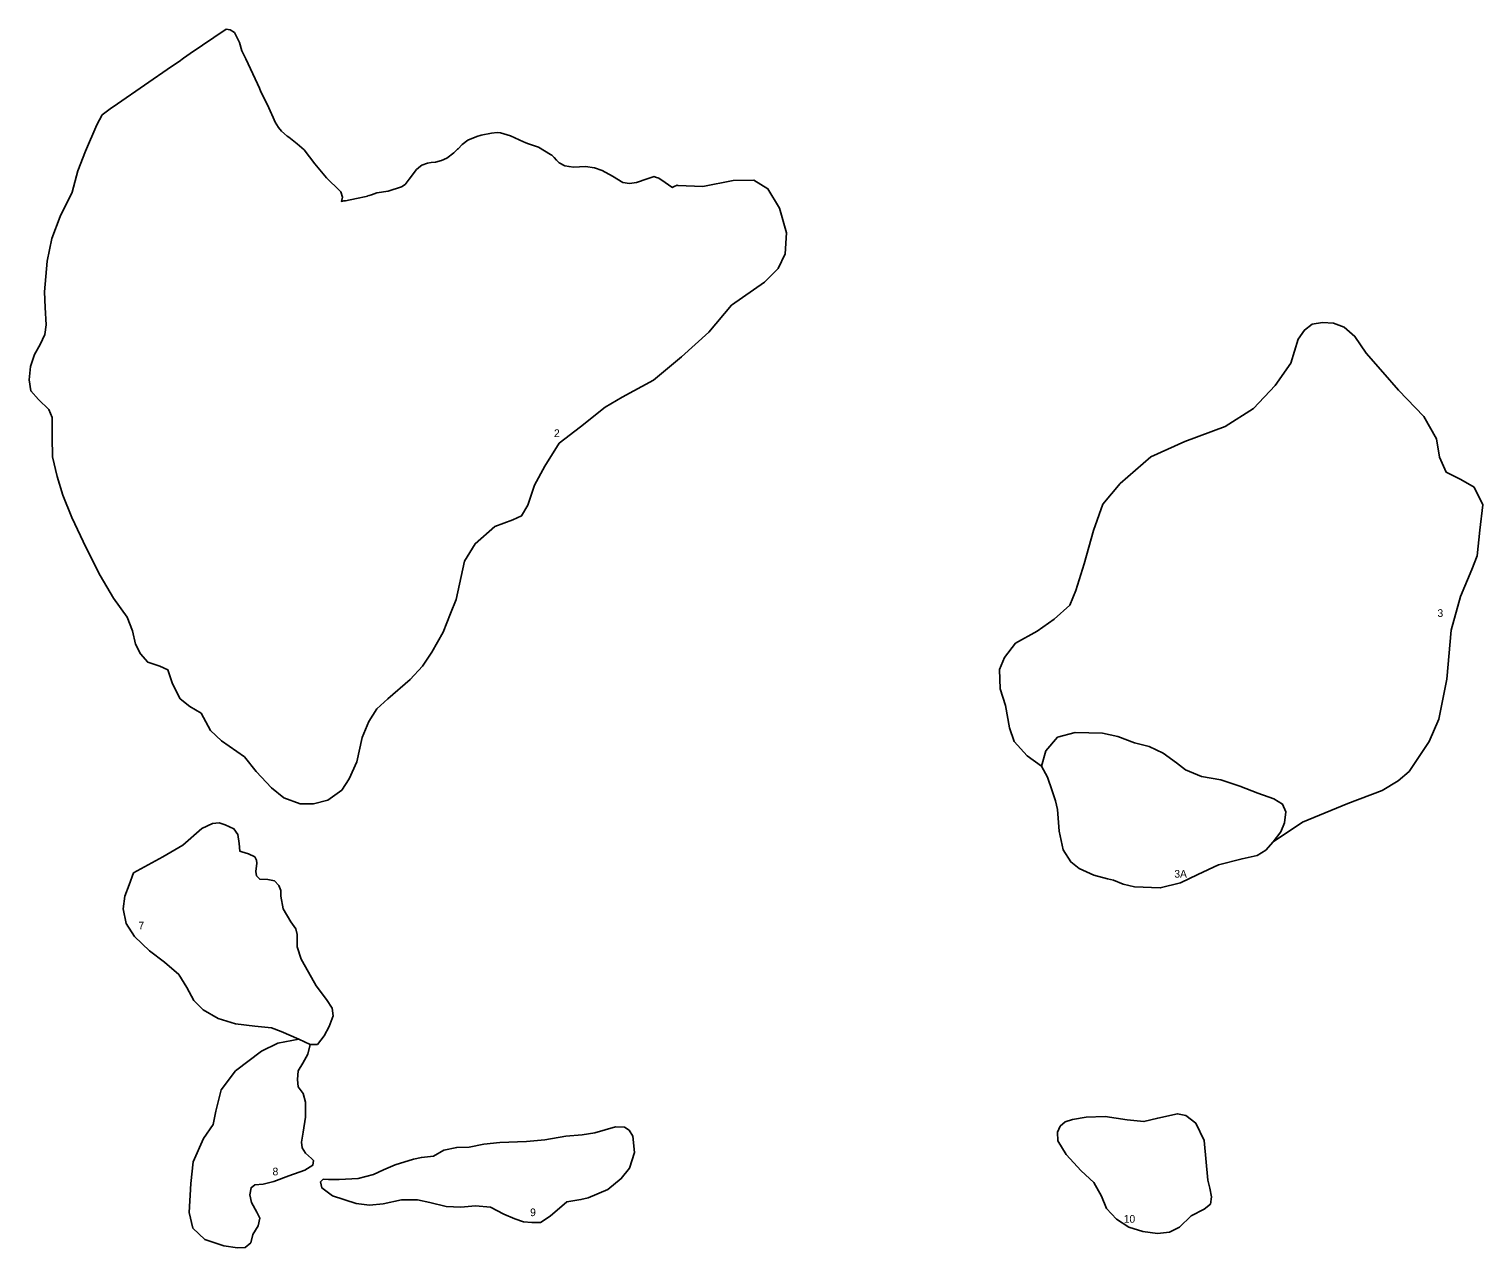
# Model space of a CAD drawing. Extents: x -439069 to -431150, y -1130245 to -1119273.
# Drawn here: x -437725 to -435457, y -1123060 to -1121158 of the extents above; entities that cross this region are included whole.
import ezdxf

# ---------------------------------------------------------------- set-up
doc = ezdxf.new("R2010")
doc.units = 0
doc.layers.add('svahové nestability přírodního charakteru dočasně uklidněné', color=7, linetype='Continuous')
doc.layers.add('Svahové nestability přírodního charakteru uklidněné', color=7, linetype='Continuous')

msp = doc.modelspace()

# ---------------------------------------------------------------- linework, layer by layer
at = {"layer": 'svahové nestability přírodního charakteru dočasně uklidněné'}
for points in [[(-436092.6, -1122255.6), (-436120.3, -1122262.8), (-436138.5, -1122284.4), (-436145.3, -1122308), (-436135.9, -1122325.3), (-436128.7, -1122346.5), (-436123.4, -1122362.3), (-436120.3, -1122375.5), (-436117.7, -1122409.4), (-436111.7, -1122438.7), (-436099.6, -1122457.4), (-436086.3, -1122467.9), (-436063.5, -1122477.9), (-436042.1, -1122483.8), (-436032.8, -1122485.7), (-436018, -1122492.2), (-436000, -1122496.5), (-435960, -1122497.9), (-435928.7, -1122490.3), (-435901.2, -1122477.2), (-435869.3, -1122462), (-435832.5, -1122452.5), (-435809.1, -1122447.2), (-435795.5, -1122438.9), (-435783.9, -1122426.2), (-435772, -1122410.6), (-435766.2, -1122396.3), (-435764.2, -1122379.4), (-435769.2, -1122367.2), (-435782.7, -1122359), (-435807.9, -1122350), (-435836, -1122339.5), (-435865.3, -1122329.5), (-435895.6, -1122324.2), (-435920.8, -1122313.9), (-435934.6, -1122302.8), (-435955.3, -1122287.6), (-435977.5, -1122277.6), (-436000, -1122271.7), (-436026.4, -1122262), (-436050.2, -1122256.5), (-436092.6, -1122255.6)], [(-435920.2, -1122852.8), (-435933.4, -1122850.2), (-435963.9, -1122857.1), (-435985.5, -1122862.6), (-436011.7, -1122860), (-436045.9, -1122854.8), (-436075.4, -1122855.5), (-436096.9, -1122859.5), (-436108.5, -1122862.7), (-436116.3, -1122869.9), (-436120.1, -1122878.9), (-436119.6, -1122892.3), (-436106.8, -1122914), (-436083.5, -1122939.1), (-436063.8, -1122957.7), (-436051.5, -1122978.8), (-436043.7, -1122998), (-436028.5, -1123014.7), (-436009.3, -1123027.1), (-435987.2, -1123034), (-435964.2, -1123037.3), (-435945.4, -1123035.2), (-435929.8, -1123027.1), (-435911.9, -1123009.4), (-435891.4, -1122999.1), (-435881.5, -1122991.1), (-435880.1, -1122979.9), (-435882.7, -1122966.3), (-435885.8, -1122954.1), (-435891.8, -1122892.2), (-435904.6, -1122864.8), (-435920.2, -1122852.8)]]:
    msp.add_lwpolyline(points, dxfattribs=at)
at = {"layer": 'Svahové nestability přírodního charakteru uklidněné'}
for points in [[(-437502.3, -1121216.6), (-437586.7, -1121275), (-437598, -1121282.9), (-437610.4, -1121292.2), (-437618.9, -1121307.6), (-437636.4, -1121349), (-437648.7, -1121379.5), (-437657.5, -1121412.7), (-437676.2, -1121450.7), (-437688.9, -1121484.9), (-437696.2, -1121520.3), (-437700.8, -1121568.2), (-437699.6, -1121592.8), (-437697.9, -1121619.8), (-437699.9, -1121634.9), (-437707.2, -1121650.4), (-437716.1, -1121665.8), (-437722.2, -1121684.5), (-437724.6, -1121705.7), (-437722.1, -1121722.8), (-437710.1, -1121736), (-437693.8, -1121751.8), (-437688.6, -1121764.5), (-437688.8, -1121795.1), (-437688.1, -1121825.8), (-437680.6, -1121856.3), (-437672.1, -1121885.3), (-437658, -1121920.1), (-437635.7, -1121967.8), (-437613.8, -1122010.8), (-437592.9, -1122046.2), (-437571.4, -1122075.5), (-437563.2, -1122096.8), (-437558.7, -1122117.8), (-437550.7, -1122133), (-437539.5, -1122146.1), (-437520.8, -1122152.2), (-437508.2, -1122157.8), (-437500.8, -1122179.8), (-437488.8, -1122203), (-437473.7, -1122214.9), (-437456.1, -1122225.5), (-437441.4, -1122252.6), (-437424.3, -1122268.5), (-437388.7, -1122293.6), (-437370.6, -1122316.4), (-437346.6, -1122342.1), (-437327.1, -1122357.4), (-437301.8, -1122367), (-437281.1, -1122367.1), (-437258.5, -1122361.2), (-437236.5, -1122345.4), (-437225.2, -1122327.9), (-437213.2, -1122301.2), (-437204.8, -1122263.6), (-437194.4, -1122238.4), (-437182.2, -1122218.7), (-437164.9, -1122203.2), (-437130.3, -1122173), (-437111.1, -1122152.3), (-437096.3, -1122130.5), (-437078.5, -1122098.9), (-437067.1, -1122070), (-437058.5, -1122048.4), (-437045.3, -1121988.2), (-437028.6, -1121961.2), (-436998.2, -1121934.5), (-436969.8, -1121923.7), (-436956.3, -1121917.8), (-436946.5, -1121901), (-436936.4, -1121869.6), (-436920.3, -1121840.3), (-436897.6, -1121804.5), (-436864.2, -1121778.8), (-436825.8, -1121748.1), (-436799.3, -1121732.6), (-436750.4, -1121705.8), (-436707, -1121669.4), (-436664.2, -1121631.4), (-436628.7, -1121589), (-436577.6, -1121553.2), (-436556, -1121531.9), (-436545, -1121509.1), (-436543.2, -1121476.3), (-436554, -1121437.9), (-436572.2, -1121407.4), (-436594.2, -1121394.1), (-436626.4, -1121394.7), (-436673.8, -1121404), (-436712.8, -1121402.4), (-436713.7, -1121402), (-436718.4, -1121404.2), (-436721.3, -1121405.6), (-436722.2, -1121404.9), (-436732.1, -1121397.9), (-436742.1, -1121391.2), (-436747.6, -1121389.2), (-436749.6, -1121388.6), (-436760.4, -1121391.9), (-436777, -1121397.7), (-436788.2, -1121399.2), (-436798.5, -1121397.8), (-436814.7, -1121387.6), (-436830.8, -1121379.1), (-436842.5, -1121374.7), (-436856.6, -1121372.7), (-436875.4, -1121373.7), (-436882.3, -1121373), (-436889, -1121371.5), (-436897.7, -1121367.1), (-436902.1, -1121362.8), (-436905.5, -1121358.9), (-436909.4, -1121355.3), (-436911.3, -1121353.8), (-436929.7, -1121342.7), (-436946.9, -1121337), (-436950.9, -1121335.1), (-436953.2, -1121334.3), (-436973.6, -1121324.7), (-436989.1, -1121320.1), (-436994.2, -1121319.6), (-437003.3, -1121320.8), (-437019.4, -1121323.8), (-437026.1, -1121325.9), (-437040.2, -1121331.9), (-437048.9, -1121338.6), (-437055.5, -1121345.1), (-437056.4, -1121345.8), (-437062.1, -1121351.2), (-437073.1, -1121359.5), (-437081.4, -1121363.3), (-437090.8, -1121365.8), (-437097.2, -1121366.5), (-437102.9, -1121367.3), (-437111.9, -1121370.8), (-437114.1, -1121372.4), (-437120.1, -1121377.4), (-437131.9, -1121392.6), (-437138.2, -1121400.6), (-437143.8, -1121404.4), (-437164.2, -1121411), (-437182.1, -1121414), (-437190.6, -1121416.9), (-437194.2, -1121418), (-437196.2, -1121418.7), (-437196.8, -1121418.8), (-437198.8, -1121419.5), (-437213.7, -1121422.5), (-437231.2, -1121426.1), (-437233.5, -1121426.5), (-437237.4, -1121427.3), (-437235.9, -1121420.6), (-437238.1, -1121412.5), (-437240, -1121410.5), (-437260.4, -1121390.6), (-437279.1, -1121368.7), (-437295.3, -1121347), (-437306.2, -1121337.3), (-437319.6, -1121326.9), (-437322.1, -1121325.2), (-437330.7, -1121317.8), (-437335.7, -1121312.1), (-437340.8, -1121303.8), (-437344, -1121296.3), (-437348.5, -1121285.8), (-437350.8, -1121281.2), (-437359.9, -1121261.9), (-437362.9, -1121256.3), (-437365.1, -1121250.8), (-437368.3, -1121244), (-437386.4, -1121204.6), (-437386.4, -1121204.6), (-437392.6, -1121192.2), (-437396.3, -1121179.4), (-437404.4, -1121163.7), (-437411, -1121159.5), (-437417.4, -1121158.4), (-437473.2, -1121196.6), (-437483.5, -1121203.7), (-437490.6, -1121208.8), (-437502.3, -1121216.6)], [(-435772, -1122410.6), (-435783.9, -1122426.2), (-435738.4, -1122395.6), (-435667.6, -1122366.3), (-435614.1, -1122346.3), (-435588.7, -1122331.2), (-435571.7, -1122316.2), (-435540.6, -1122269.5), (-435525.6, -1122234.7), (-435513.1, -1122172.3), (-435506.2, -1122096.2), (-435491.6, -1122043.5), (-435474.1, -1122001.3), (-435465.8, -1121980.2), (-435461.7, -1121939.9), (-435456.7, -1121900.5), (-435470.6, -1121872.9), (-435491.4, -1121860.9), (-435514.2, -1121849.6), (-435524.6, -1121826.1), (-435529, -1121797.4), (-435549, -1121762.7), (-435588.3, -1121721.8), (-435612.6, -1121693.4), (-435638.6, -1121663.9), (-435656.4, -1121637.9), (-435673.3, -1121623.3), (-435689.8, -1121617.3), (-435706.7, -1121616), (-435723, -1121618.5), (-435735.1, -1121627.9), (-435744.8, -1121642.3), (-435756.2, -1121679.3), (-435780.7, -1121714.2), (-435814.8, -1121750.3), (-435858.6, -1121778.1), (-435921.9, -1121801.5), (-435974.9, -1121825.7), (-436022.6, -1121867.3), (-436049.7, -1121899.3), (-436064.3, -1121940.7), (-436078.8, -1121992.5), (-436091.5, -1122034.1), (-436100.9, -1122057), (-436125.3, -1122078.7), (-436152.3, -1122097.4), (-436186, -1122116.5), (-436202.9, -1122138.8), (-436211, -1122157.1), (-436209.6, -1122187.5), (-436201.2, -1122213.7), (-436195.4, -1122248.2), (-436187.7, -1122269.6), (-436167.7, -1122292), (-436145.3, -1122308), (-436138.5, -1122284.4), (-436120.3, -1122262.8), (-436092.6, -1122255.6), (-436050.2, -1122256.5), (-436026.4, -1122262), (-436000, -1122271.7), (-435977.5, -1122277.6), (-435955.3, -1122287.6), (-435934.6, -1122302.8), (-435920.8, -1122313.9), (-435895.6, -1122324.2), (-435865.3, -1122329.5), (-435836, -1122339.5), (-435807.9, -1122350), (-435782.7, -1122359), (-435769.2, -1122367.2), (-435764.2, -1122379.4), (-435766.2, -1122396.3), (-435772, -1122410.6)], [(-437303.6, -1122733.8), (-437286.2, -1122742.2), (-437274.8, -1122742.3), (-437264.1, -1122729), (-437256.3, -1122714.2), (-437250.1, -1122697.5), (-437251.8, -1122685.5), (-437260.9, -1122672), (-437276.8, -1122650.5), (-437288.8, -1122629.3), (-437300, -1122609.1), (-437306.4, -1122589.7), (-437306.2, -1122570.7), (-437308.6, -1122561.7), (-437316.5, -1122551), (-437328.1, -1122530.7), (-437332, -1122510.9), (-437332, -1122502.3), (-437334.9, -1122494.5), (-437341.6, -1122487.2), (-437352.4, -1122484.8), (-437364.9, -1122484.4), (-437370.1, -1122479.1), (-437371.1, -1122472.2), (-437369.3, -1122459.4), (-437369.6, -1122454.9), (-437372.6, -1122449.5), (-437382.2, -1122444.9), (-437392.6, -1122441.6), (-437396.1, -1122440.5), (-437397.1, -1122428.6), (-437398.8, -1122414.6), (-437405, -1122405.8), (-437418.5, -1122399.4), (-437428, -1122396.5), (-437438.3, -1122397.6), (-437455, -1122405.5), (-437484.6, -1122431.5), (-437515.9, -1122449.7), (-437561.5, -1122474.5), (-437568.3, -1122493.3), (-437575.3, -1122510.8), (-437577.8, -1122530.9), (-437573, -1122553.7), (-437560.4, -1122573.6), (-437536.7, -1122596.2), (-437513.4, -1122613.9), (-437491.2, -1122633.2), (-437478.7, -1122653.6), (-437467.5, -1122673.8), (-437453.2, -1122688.2), (-437429.6, -1122701.5), (-437402.5, -1122709.8), (-437372.5, -1122713.9), (-437346.3, -1122716.4), (-437331.3, -1122722), (-437303.6, -1122733.8)], [(-437303.6, -1122733.8), (-437336.7, -1122740), (-437362.3, -1122752.5), (-437402.6, -1122783.3), (-437424.8, -1122813.2), (-437433.1, -1122846.5), (-437437.4, -1122867.3), (-437452.3, -1122889), (-437468.8, -1122925.5), (-437472.4, -1122959.2), (-437475, -1123004.3), (-437469.1, -1123029), (-437450.6, -1123046.3), (-437421, -1123056.5), (-437399.3, -1123059.6), (-437387.3, -1123058.7), (-437378.8, -1123051.5), (-437375.6, -1123038.5), (-437367.5, -1123025.1), (-437364.8, -1123013.4), (-437369.3, -1123003.8), (-437377.4, -1122988.6), (-437380, -1122977), (-437378.2, -1122965.7), (-437372.2, -1122961.3), (-437359.3, -1122960.1), (-437342.7, -1122956.2), (-437319.5, -1122947), (-437294.2, -1122938.4), (-437282.1, -1122930.5), (-437281.1, -1122923.1), (-437284, -1122920.3), (-437293.4, -1122911.6), (-437298.5, -1122903.7), (-437299.6, -1122894.8), (-437297, -1122879.2), (-437293.4, -1122855.7), (-437293.3, -1122832.4), (-437297.1, -1122818.9), (-437304.6, -1122808.1), (-437305.9, -1122796.6), (-437304.9, -1122783.5), (-437297.8, -1122771.3), (-437289.6, -1122757.4), (-437286.2, -1122742.2), (-437303.6, -1122733.8)], [(-436795.8, -1122871.1), (-436809.9, -1122870.9), (-436842.3, -1122879.8), (-436861.9, -1122883.1), (-436887.2, -1122885), (-436920.2, -1122891.2), (-436948.6, -1122893.4), (-436990.5, -1122894.9), (-437015.4, -1122897.8), (-437038.2, -1122902.2), (-437057.6, -1122902.9), (-437077.8, -1122907), (-437093.9, -1122916.3), (-437112.6, -1122918.4), (-437125.1, -1122921.3), (-437153.5, -1122930.1), (-437171.8, -1122937.9), (-437187.3, -1122945.1), (-437211.1, -1122951.1), (-437240.7, -1122952.7), (-437257.5, -1122952.7), (-437265.8, -1122952.1), (-437270.1, -1122956.6), (-437267.7, -1122966), (-437251.5, -1122978.3), (-437214.6, -1122990.4), (-437193.7, -1122993), (-437172.4, -1122990.7), (-437143.7, -1122984.6), (-437118.7, -1122984.8), (-437099.6, -1122988.9), (-437074.1, -1122994.9), (-437051.3, -1122995.8), (-437028.2, -1122993.7), (-437004.6, -1122996), (-436983.9, -1123006.8), (-436966.9, -1123014.3), (-436953.2, -1123018.9), (-436940.5, -1123019.9), (-436926.8, -1123019.7), (-436912, -1123009.9), (-436885.6, -1122987.7), (-436863.7, -1122984.2), (-436852.5, -1122981.5), (-436822, -1122968.5), (-436800.8, -1122951.3), (-436788.1, -1122935.1), (-436780, -1122910.6), (-436782.9, -1122885.3), (-436788.3, -1122876.1), (-436795.8, -1122871.1)]]:
    msp.add_lwpolyline(points, dxfattribs=at)

# ---------------------------------------------------------------- texts
at = {"layer": 'svahové nestability přírodního charakteru dočasně uklidněné'}
for s, p in [('3A', (-435938.1, -1122482)), ('10', (-436017, -1123020.3))]:
    msp.add_text(s, height=12, dxfattribs=at).set_placement(p)
at = {"layer": 'Svahové nestability přírodního charakteru uklidněné'}
for s, p in [('2', (-436905.8, -1121794.8)), ('3', (-435527.6, -1122075.3)), ('7', (-437554, -1122562.7)), ('8', (-437344.8, -1122946.4)), ('9', (-436943, -1123010))]:
    msp.add_text(s, height=12, dxfattribs=at).set_placement(p)

doc.saveas('drawing.dxf')
